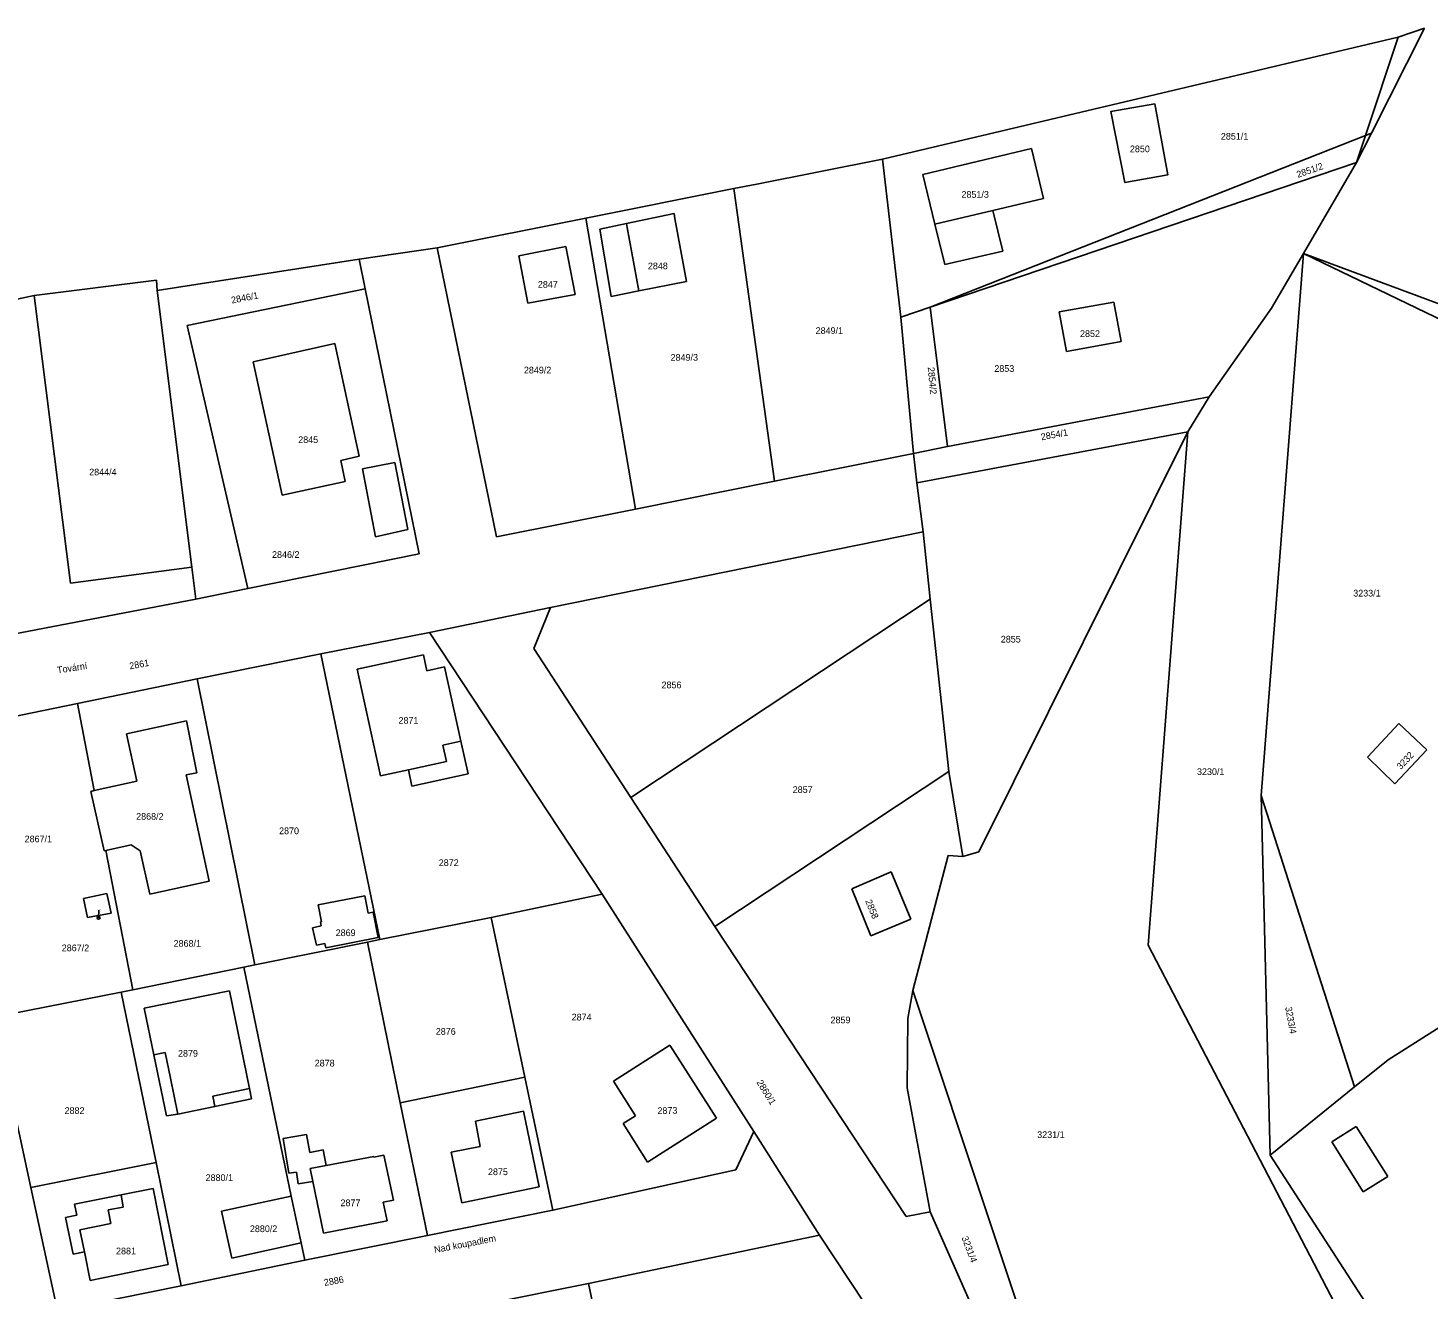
# Model space of a CAD drawing. Extents: x -722132 to -721608, y -1046877 to -1046449.
# Drawn here: x -721988.9 to -721811.3, y -1046613 to -1046453 of the extents above; entities that cross this region are included whole.
import ezdxf

# ---------------------------------------------------------------- set-up
doc = ezdxf.new("R2010")
doc.units = 0
for name, color, linetype in [('Vrstva 1', 7, 'Continuous'), ('Vrstva 15', 7, 'Continuous'), ('Vrstva 16', 7, 'Continuous'), ('Vrstva 18', 7, 'Continuous'), ('Vrstva 19', 7, 'Continuous'), ('Vrstva 4', 7, 'Continuous'), ('Vrstva 6', 7, 'Continuous')]:
    doc.layers.add(name, color=color, linetype=linetype)

msp = doc.modelspace()

# ---------------------------------------------------------------- linework, layer by layer
at = {"layer": 'Vrstva 1'}
for p, q in [((-721875.44, -1046471.53), (-721861.62, -1046468.23)), ((-721861.62, -1046468.23), (-721860.11, -1046474.57)), ((-721873.9, -1046477.85), (-721875.44, -1046471.53)), ((-721860.11, -1046474.57), (-721866.53, -1046476.09)), ((-721913, -1046477.76), (-721906.98, -1046476.5)), ((-721906.98, -1046476.5), (-721906.87, -1046477.12)), ((-721866.53, -1046476.09), (-721865.29, -1046481.25)), ((-721916.38, -1046478.47), (-721913, -1046477.76)), ((-721914.95, -1046487), (-721916.38, -1046478.47)), ((-721872.65, -1046482.97), (-721873.9, -1046477.85)), ((-721865.29, -1046481.25), (-721872.65, -1046482.97)), ((-721911.45, -1046486.31), (-721914.95, -1046487)), ((-721976.45, -1046542.48), (-721968.84, -1046540.83)), ((-721968.84, -1046540.83), (-721967.53, -1046547.42)), ((-721975.12, -1046548.5), (-721976.45, -1046542.48)), ((-721967.53, -1046547.42), (-721968.88, -1046547.71)), ((-721968.88, -1046547.71), (-721965.94, -1046561.2)), ((-721980.99, -1046549.79), (-721980.53, -1046549.69)), ((-721979.27, -1046557.35), (-721980.99, -1046549.79)), ((-721980.53, -1046549.69), (-721975.12, -1046548.5)), ((-721975.87, -1046556.59), (-721979.05, -1046557.3)), ((-721974.71, -1046557.34), (-721975.87, -1046556.59)), ((-721979.05, -1046557.3), (-721979.27, -1046557.35)), ((-721973.48, -1046562.85), (-721974.71, -1046557.34)), ((-721965.94, -1046561.2), (-721973.48, -1046562.85)), ((-721961.58, -1046572.1), (-721955.54, -1046601.12)), ((-721974.21, -1046577.31), (-721963.38, -1046575.09)), ((-721963.38, -1046575.09), (-721960.84, -1046587.49)), ((-721972.98, -1046583.23), (-721974.21, -1046577.31)), ((-721971.37, -1046590.96), (-721972.98, -1046583.23)), ((-721960.57, -1046588.8), (-721965.24, -1046589.76)), ((-721960.84, -1046587.49), (-721960.57, -1046588.8)), ((-721969.92, -1046590.72), (-721971.37, -1046590.96)), ((-721965.24, -1046589.76), (-721969.92, -1046590.72)), ((-721955.54, -1046601.12), (-721964.38, -1046603.04)), ((-721955.54, -1046601.12), (-721954.3, -1046607.08)), ((-721964.38, -1046603.04), (-721963.1, -1046609)), ((-721963.1, -1046609), (-721954.3, -1046607.08)), ((-721954.3, -1046607.08), (-721953.84, -1046609.27))]:
    msp.add_line(p, q, dxfattribs=at)
for points in [[(-721818.51, -1046466.3), (-721811.77, -1046452.95)], [(-721815.12, -1046454.12), (-721811.77, -1046452.95)], [(-721880.55, -1046469.58), (-721815.12, -1046454.12)], [(-721845.98, -1046462.58), (-721844.33, -1046471.57), (-721849.78, -1046472.56), (-721851.59, -1046463.55), (-721845.98, -1046462.58)], [(-721820.39, -1046470.01), (-721818.51, -1046466.3)], [(-721896.48, -1046472.75), (-721880.55, -1046469.58)], [(-721880.55, -1046469.58), (-721878.2, -1046489.65)], [(-721874.48, -1046488.36), (-721820.39, -1046470.01)], [(-721827.15, -1046481.57), (-721820.39, -1046470.01)], [(-721918.19, -1046477.07), (-721899.38, -1046473.33)], [(-721899.38, -1046473.33), (-721896.48, -1046472.75)], [(-721899.38, -1046473.33), (-721894.24, -1046510.45)], [(-721937.02, -1046480.82), (-721918.19, -1046477.07)], [(-721918.19, -1046477.07), (-721911.89, -1046513.99)], [(-721906.87, -1046477.12), (-721905.41, -1046485.12)], [(-721972.56, -1046486.27), (-721946.92, -1046482.26)], [(-721946.92, -1046482.26), (-721937.02, -1046480.82)], [(-721946.92, -1046482.26), (-721946.15, -1046486.03)], [(-721937.02, -1046480.82), (-721929.52, -1046517.52)], [(-721926.69, -1046481.85), (-721920.71, -1046480.65)], [(-721926.69, -1046481.85), (-721925.54, -1046487.87)], [(-721920.71, -1046480.65), (-721919.54, -1046486.74)], [(-721831.18, -1046488.48), (-721827.15, -1046481.57)], [(-721988.16, -1046486.9), (-721972.65, -1046484.96)], [(-721972.65, -1046484.96), (-721972.56, -1046486.27)], [(-721911.45, -1046486.31), (-721905.41, -1046485.12)], [(-722071.04, -1046504.79), (-721988.16, -1046486.9)], [(-721988.16, -1046486.9), (-721983.55, -1046523.36)], [(-721972.56, -1046486.27), (-721968.14, -1046521.34)], [(-721968.75, -1046490.69), (-721946.15, -1046486.03)], [(-721946.15, -1046486.03), (-721939.3, -1046519.64)], [(-721925.54, -1046487.87), (-721919.54, -1046486.74)], [(-721858.12, -1046488.94), (-721851.21, -1046487.71)], [(-721851.21, -1046487.71), (-721850.26, -1046492.7)], [(-721878.2, -1046489.65), (-721874.48, -1046488.36)], [(-721874.48, -1046488.36), (-721872.28, -1046506.04)], [(-721858.12, -1046488.94), (-721857.2, -1046494)], [(-721839.1, -1046499.76), (-721831.18, -1046488.48)], [(-721968.75, -1046490.69), (-721961.04, -1046524.05)], [(-721878.2, -1046489.65), (-721876.59, -1046506.91)], [(-721960.38, -1046495.29), (-721950, -1046492.98)], [(-721950, -1046492.98), (-721946.93, -1046507.28)], [(-721857.2, -1046494), (-721850.26, -1046492.7)], [(-721960.38, -1046495.29), (-721956.69, -1046512.2)], [(-721872.28, -1046506.04), (-721839.1, -1046499.76)], [(-721841.82, -1046504.18), (-721839.1, -1046499.76)], [(-721876.2, -1046510.63), (-721841.82, -1046504.18)], [(-721868.3, -1046557.45), (-721841.82, -1046504.18)], [(-721894.24, -1046510.45), (-721876.59, -1046506.91)], [(-721876.59, -1046506.91), (-721872.28, -1046506.04)], [(-721876.59, -1046506.91), (-721876.2, -1046510.63)], [(-721949.26, -1046507.81), (-721946.93, -1046507.28)], [(-721949.26, -1046507.81), (-721948.69, -1046510.46)], [(-721956.69, -1046512.2), (-721948.69, -1046510.46)], [(-721911.89, -1046513.99), (-721894.24, -1046510.45)], [(-721876.2, -1046510.63), (-721875.39, -1046516.88)], [(-721929.52, -1046517.52), (-721911.89, -1046513.99)], [(-721922.67, -1046526.46), (-721875.39, -1046516.88)], [(-721875.39, -1046516.88), (-721874.47, -1046525.42)], [(-721961.04, -1046524.05), (-721939.3, -1046519.64)], [(-721983.55, -1046523.36), (-721968.14, -1046521.34)], [(-721968.14, -1046521.34), (-721967.65, -1046525.4)], [(-721967.65, -1046525.4), (-721961.04, -1046524.05)], [(-722051.77, -1046541.52), (-721967.65, -1046525.4)], [(-721938.01, -1046529.63), (-721922.67, -1046526.46)], [(-721924.79, -1046531.65), (-721922.67, -1046526.46)], [(-721874.47, -1046525.42), (-721872.11, -1046547.25)], [(-721951.79, -1046532.34), (-721938.01, -1046529.63)], [(-721938.01, -1046529.63), (-721916.09, -1046562.81)], [(-721924.79, -1046531.65), (-721912.47, -1046550.56)], [(-721967.46, -1046535.52), (-721951.79, -1046532.34)], [(-721951.79, -1046532.34), (-721944.32, -1046568.57)], [(-721947.19, -1046534.27), (-721938.78, -1046532.45)], [(-721938.78, -1046532.45), (-721938.35, -1046534.49)], [(-721982.68, -1046538.64), (-721967.46, -1046535.52)], [(-721967.46, -1046535.52), (-721960.17, -1046571.8)], [(-721947.19, -1046534.27), (-721944.23, -1046547.82)], [(-721938.35, -1046534.49), (-721936.1, -1046533.99)], [(-721936.1, -1046533.99), (-721934.05, -1046543.44)], [(-721998.72, -1046541.93), (-721982.68, -1046538.64)], [(-721818.99, -1046545.43), (-721815.02, -1046541.16)], [(-721815.02, -1046541.16), (-721811.47, -1046544.51)], [(-721934.05, -1046543.44), (-721933.09, -1046547.58)], [(-721815.54, -1046548.82), (-721811.47, -1046544.51)], [(-721818.99, -1046545.43), (-721815.54, -1046548.82)], [(-721944.23, -1046547.82), (-721940.69, -1046547.05)], [(-721940.69, -1046547.05), (-721940.25, -1046549.11)], [(-721940.25, -1046549.11), (-721933.09, -1046547.58)], [(-721901.81, -1046566.91), (-721872.11, -1046547.25)], [(-721872.11, -1046547.25), (-721870.34, -1046558.05)], [(-721912.47, -1046550.56), (-721901.81, -1046566.91)], [(-721876.68, -1046575.04), (-721872.2, -1046557.91)], [(-721872.2, -1046557.91), (-721870.34, -1046558.05)], [(-721870.34, -1046558.05), (-721868.3, -1046557.45)], [(-721884.42, -1046562.15), (-721879.45, -1046560.01)], [(-721879.45, -1046560.01), (-721876.94, -1046566.02)], [(-721884.42, -1046562.15), (-721882.02, -1046568.13)], [(-721981.92, -1046563.4), (-721978.92, -1046562.73)], [(-721981.92, -1046563.4), (-721981.39, -1046565.78)], [(-721978.92, -1046562.73), (-721978.37, -1046565.23)], [(-721952.14, -1046564.18), (-721946.2, -1046563.05)], [(-721946.2, -1046563.05), (-721945.78, -1046565.23)], [(-721930.19, -1046565.79), (-721916.09, -1046562.81)], [(-721916.09, -1046562.81), (-721896.88, -1046592.92)], [(-721981.39, -1046565.78), (-721978.37, -1046565.23)], [(-721952.14, -1046564.18), (-721951.69, -1046566.32)], [(-721945.78, -1046565.23), (-721945.15, -1046565.11)], [(-721945.15, -1046565.11), (-721944.52, -1046568.34)], [(-721944.32, -1046568.57), (-721930.19, -1046565.79)], [(-721930.19, -1046565.79), (-721925.92, -1046586.06)], [(-721816.4, -1046583.83), (-721785.73, -1046564.38)], [(-721952.83, -1046567.08), (-721951.74, -1046566.85)], [(-721952.83, -1046567.08), (-721952.36, -1046569.32)], [(-721951.85, -1046566.36), (-721951.69, -1046566.32)], [(-721951.85, -1046566.36), (-721951.74, -1046566.85)], [(-721901.81, -1046566.91), (-721877.54, -1046603.71)], [(-721882.02, -1046568.13), (-721876.94, -1046566.02)], [(-721960.17, -1046571.8), (-721945.89, -1046568.91)], [(-721952.36, -1046569.32), (-721951.28, -1046569.1)], [(-721951.28, -1046569.1), (-721951.17, -1046569.63)], [(-721951.17, -1046569.63), (-721944.52, -1046568.34)], [(-721945.89, -1046568.91), (-721944.32, -1046568.57)], [(-721945.89, -1046568.91), (-721941.72, -1046589.28)], [(-721975.62, -1046574.98), (-721961.58, -1046572.1)], [(-721961.58, -1046572.1), (-721960.17, -1046571.8)], [(-721991.32, -1046578.06), (-721977.1, -1046575.28)], [(-721977.1, -1046575.28), (-721975.62, -1046574.98)], [(-721977.1, -1046575.28), (-721972.7, -1046596.88)], [(-721877.34, -1046578.6), (-721876.68, -1046575.04)], [(-721993.21, -1046578.75), (-721988.59, -1046600.03)], [(-721877.41, -1046587.38), (-721877.34, -1046578.6)], [(-721914.68, -1046586.54), (-721907.53, -1046581.98)], [(-721907.53, -1046581.98), (-721901.61, -1046591.26)], [(-721820.66, -1046587.28), (-721816.4, -1046583.83)], [(-721941.72, -1046589.28), (-721925.92, -1046586.06)], [(-721925.92, -1046586.06), (-721922.37, -1046602.93)], [(-721914.68, -1046586.54), (-721911.89, -1046590.93)], [(-721877.41, -1046587.38), (-721874.47, -1046603.13)], [(-721831.36, -1046595.92), (-721820.66, -1046587.28)], [(-721941.72, -1046589.28), (-721938.27, -1046606.14)], [(-721913.43, -1046591.91), (-721911.89, -1046590.93)], [(-721913.43, -1046591.91), (-721910.33, -1046596.82)], [(-721910.33, -1046596.82), (-721901.61, -1046591.26)], [(-721956.57, -1046593.82), (-721953.61, -1046593.3)], [(-721956.57, -1046593.82), (-721955.84, -1046598.23)], [(-721953.61, -1046593.3), (-721953.19, -1046595.58)], [(-721899.16, -1046597.81), (-721896.88, -1046592.92)], [(-721896.88, -1046592.92), (-721888.51, -1046606.08)], [(-721953.19, -1046595.58), (-721951.49, -1046595.26)], [(-721951.49, -1046595.26), (-721951.11, -1046597.25)], [(-721945.05, -1046596.21), (-721943.8, -1046595.93)], [(-721943.8, -1046595.93), (-721942.58, -1046601.65)], [(-721831.36, -1046595.92), (-721817.41, -1046617.52)], [(-721988.59, -1046600.03), (-721972.7, -1046596.88)], [(-721972.7, -1046596.88), (-721969.52, -1046612.5)], [(-721951.11, -1046597.25), (-721945.07, -1046596.11)], [(-721945.07, -1046596.11), (-721945.05, -1046596.21)], [(-721922.37, -1046602.93), (-721899.16, -1046597.81)], [(-721955.84, -1046598.23), (-721954.87, -1046598.09)], [(-721954.87, -1046598.09), (-721954.66, -1046599.56)], [(-721954.66, -1046599.56), (-721952.8, -1046599.26)], [(-721952.8, -1046599.26), (-721951.46, -1046605.84)], [(-721988.59, -1046600.03), (-721985.2, -1046615.68)], [(-721943.87, -1046601.92), (-721942.58, -1046601.65)], [(-721943.87, -1046601.92), (-721943.36, -1046604.28)], [(-721938.27, -1046606.14), (-721922.37, -1046602.93)], [(-721877.54, -1046603.71), (-721874.47, -1046603.13)], [(-721874.47, -1046603.13), (-721859.95, -1046636.08)], [(-721951.46, -1046605.84), (-721943.36, -1046604.28)], [(-721953.84, -1046609.27), (-721938.27, -1046606.14)], [(-721917.82, -1046612.2), (-721888.51, -1046606.08)], [(-721888.51, -1046606.08), (-721880.83, -1046617.73)], [(-721969.52, -1046612.5), (-721953.84, -1046609.27)], [(-721985.2, -1046615.68), (-721969.52, -1046612.5)], [(-721943.34, -1046617.33), (-721917.82, -1046612.2)], [(-721917.82, -1046612.2), (-721914.52, -1046627.86)]]:
    msp.add_lwpolyline(points, dxfattribs=at)
at = {"layer": 'Vrstva 16'}
msp.add_lwpolyline([(-721979.94, -1046564.84), (-721979.98, -1046565.84)], dxfattribs=at)
msp.add_circle((-721979.98, -1046565.84), 0.175, dxfattribs=at)
at = {"layer": 'Vrstva 4'}
for p, q in [((-721873.9, -1046477.85), (-721866.53, -1046476.09)), ((-721913, -1046477.76), (-721912.91, -1046478.25)), ((-721912.91, -1046478.25), (-721911.45, -1046486.31)), ((-721971.75, -1046582.96), (-721972.98, -1046583.23)), ((-721971.53, -1046582.91), (-721971.75, -1046582.96)), ((-721970.86, -1046586.17), (-721971.53, -1046582.91)), ((-721969.92, -1046590.72), (-721970.86, -1046586.17)), ((-721965.51, -1046588.45), (-721960.84, -1046587.49)), ((-721965.24, -1046589.76), (-721965.51, -1046588.45))]:
    msp.add_line(p, q, dxfattribs=at)
for points in [[(-721819.26, -1046466.59), (-721815.12, -1046454.12)], [(-721820.39, -1046470.01), (-721819.26, -1046466.59)], [(-721946.51, -1046508.89), (-721942.41, -1046508.09)], [(-721946.51, -1046508.89), (-721944.84, -1046517.48)], [(-721942.41, -1046508.09), (-721940.76, -1046516.58)], [(-721944.84, -1046517.48), (-721940.76, -1046516.58)], [(-721936.3, -1046543.92), (-721934.05, -1046543.44)], [(-721936.3, -1046543.92), (-721935.85, -1046546)], [(-721940.69, -1046547.05), (-721935.85, -1046546)], [(-721932.18, -1046591.63), (-721926.08, -1046590.36)], [(-721926.08, -1046590.36), (-721924.09, -1046599.96)], [(-721932.18, -1046591.63), (-721931.57, -1046594.82)], [(-721823.52, -1046594.24), (-721820.44, -1046592.3)], [(-721820.44, -1046592.3), (-721816.44, -1046598.64)], [(-721823.52, -1046594.24), (-721819.56, -1046600.58)], [(-721935.27, -1046595.57), (-721931.57, -1046594.82)], [(-721935.27, -1046595.57), (-721933.91, -1046602)], [(-721953.13, -1046597.63), (-721951.11, -1046597.25)], [(-721953.13, -1046597.63), (-721952.8, -1046599.26)], [(-721819.56, -1046600.58), (-721816.44, -1046598.64)], [(-721983.04, -1046602.15), (-721977.14, -1046600.97)], [(-721977.14, -1046600.97), (-721973.07, -1046600.16)], [(-721977.14, -1046600.97), (-721976.86, -1046602.53)], [(-721973.07, -1046600.16), (-721971.15, -1046609.81)], [(-721933.91, -1046602), (-721924.09, -1046599.96)], [(-721983.04, -1046602.15), (-721982.75, -1046603.54)], [(-721978.77, -1046602.88), (-721976.86, -1046602.53)], [(-721978.77, -1046602.88), (-721978.42, -1046604.6)], [(-721984.17, -1046603.84), (-721982.75, -1046603.54)], [(-721984.17, -1046603.84), (-721983.22, -1046608.49)], [(-721982.36, -1046605.4), (-721978.42, -1046604.6)], [(-721982.36, -1046605.4), (-721981.79, -1046608.2)], [(-721983.22, -1046608.49), (-721981.79, -1046608.2)], [(-721981.79, -1046608.2), (-721981.05, -1046611.85)], [(-721981.05, -1046611.85), (-721971.15, -1046609.81)]]:
    msp.add_lwpolyline(points, dxfattribs=at)
at = {"layer": 'Vrstva 6'}
for p, q in [((-721982.68, -1046538.64), (-721980.53, -1046549.69)), ((-721979.05, -1046557.3), (-721975.62, -1046574.98))]:
    msp.add_line(p, q, dxfattribs=at)
for points in [[(-721819.26, -1046466.59), (-721818.51, -1046466.3)], [(-721874.48, -1046488.36), (-721819.26, -1046466.59)], [(-721832.52, -1046550.31), (-721827.15, -1046481.57)], [(-721827.15, -1046481.57), (-721790.7, -1046495.09)], [(-721827.15, -1046481.57), (-721792.48, -1046498.26)], [(-721846.82, -1046569.29), (-721841.82, -1046504.18)], [(-721912.47, -1046550.56), (-721874.47, -1046525.42)], [(-721832.52, -1046550.31), (-721820.66, -1046587.28)], [(-721832.52, -1046550.31), (-721831.36, -1046595.92)], [(-721846.82, -1046569.29), (-721821.61, -1046617.74)], [(-721876.68, -1046575.04), (-721856.87, -1046634.61)]]:
    msp.add_lwpolyline(points, dxfattribs=at)

# ---------------------------------------------------------------- texts
at = {"layer": 'Vrstva 15'}
for s, rotation, p in [('Tovární', 8.7225, (-721985.18, -1046534.84)), ('Nad koupadlem', 10.8974, (-721937.33, -1046608.36))]:
    msp.add_text(s, height=0.85, rotation=rotation, dxfattribs=at).set_placement(p)
at = {"layer": 'Vrstva 16'}
msp.add_text('2867/2', height=0.85, dxfattribs=at).set_placement((-721984.66, -1046570.07))
at = {"layer": 'Vrstva 18'}
for s, p in [('2851/1', (-721837.61, -1046467.11)), ('2849/1', (-721889.02, -1046491.76)), ('2849/3', (-721907.42, -1046495.16)), ('2849/2', (-721926.03, -1046496.77)), ('2853', (-721866.35, -1046496.57)), ('2846/2', (-721957.98, -1046520.17)), ('3233/1', (-721820.82, -1046525.07)), ('2855', (-721865.53, -1046530.91)), ('2856', (-721908.57, -1046536.71)), ('3230/1', (-721840.64, -1046547.72)), ('2857', (-721891.93, -1046549.99)), ('2870', (-721957.09, -1046555.22)), ('2867/1', (-721989.37, -1046556.25)), ('2872', (-721936.83, -1046559.26)), ('2868/1', (-721970.47, -1046569.5)), ('2874', (-721919.97, -1046578.85)), ('2876', (-721937.21, -1046580.67)), ('2859', (-721887.13, -1046579.21)), ('2878', (-721952.57, -1046584.69)), ('2882', (-721984.3, -1046590.71)), ('3231/1', (-721860.91, -1046593.76)), ('2880/1', (-721966.41, -1046599.22))]:
    msp.add_text(s, height=0.85, dxfattribs=at).set_placement(p)
for s, rotation, p in [('2851/2', 19.4252, (-721827.83, -1046471.97)), ('2846/1', 10.8029, (-721963.08, -1046487.91)), ('2854/2', 275.1705, (-721874.8, -1046496)), ('2854/1', 10.2844, (-721860.37, -1046505.26)), ('2861', 10.3906, (-721976, -1046534.32)), ('3233/4', 280.4997, (-721829.46, -1046577.19)), ('2860/1', 301.9227, (-721896.55, -1046586.71)), ('3231/4', 290.9239, (-721870.52, -1046606.41)), ('2886', 9.8032, (-721951.32, -1046612.53))]:
    msp.add_text(s, height=0.85, rotation=rotation, dxfattribs=at).set_placement(p)
at = {"layer": 'Vrstva 19'}
for s, height, p in [('2850', 0.85, (-721849.15, -1046468.71)), ('2851/3', 0.85, (-721870.52, -1046474.49)), ('2848', 0.85, (-721910.3, -1046483.56)), ('2847', 0.85, (-721924.26, -1046485.9)), ('2852', 0.85, (-721855.48, -1046492.15)), ('2845', 0.85, (-721954.66, -1046505.6)), ('2844/4', 0.85, (-721981.18, -1046509.7)), ('2871', 0.85, (-721941.94, -1046541.21)), ('2868/2', 0.85, (-721975.22, -1046553.39)), ('2867/2', 0.1, (-721980.15, -1046564.84)), ('2869', 0.85, (-721949.91, -1046568.15)), ('2879', 0.85, (-721969.91, -1046583.45)), ('2875', 0.85, (-721930.59, -1046598.47)), ('2877', 0.85, (-721949.3, -1046602.41)), ('2880/2', 0.85, (-721960.79, -1046605.7)), ('2881', 0.85, (-721977.77, -1046608.52))]:
    msp.add_text(s, height=height, dxfattribs=at).set_placement(p)
for s, rotation, p in [('3232', 46.839, (-721814.79, -1046547.1)), ('2858', 292.2951, (-721882.74, -1046563.71)), ('2873', 1.1347, (-721909.08, -1046590.73))]:
    msp.add_text(s, height=0.85, rotation=rotation, dxfattribs=at).set_placement(p)

doc.saveas('drawing.dxf')
